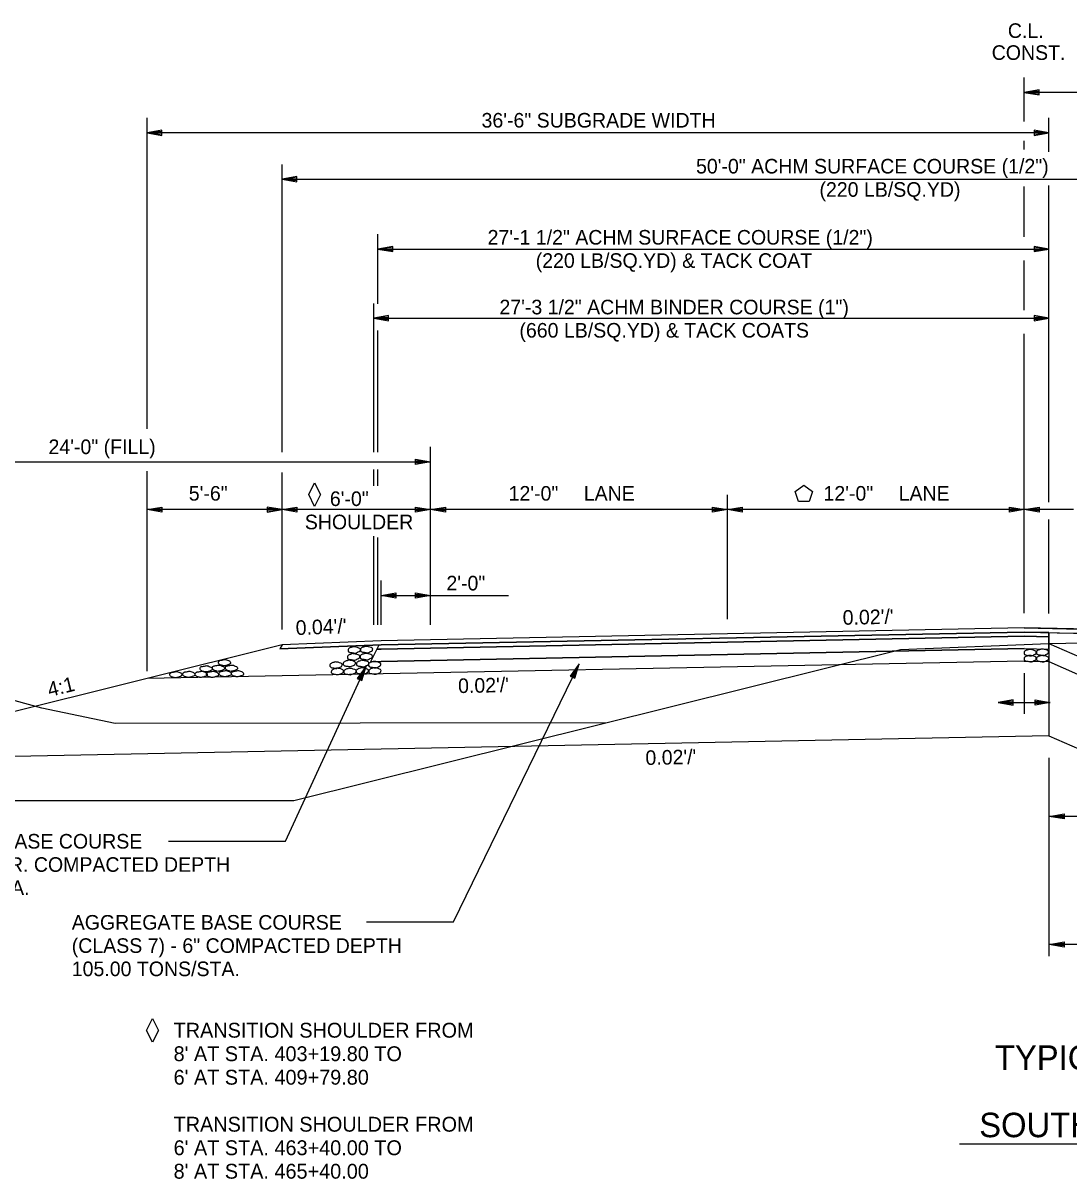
# Model space of a CAD drawing. Extents: x 1398565 to 1398920, y 1968324 to 1968581.
# Drawn here: x 1398801.5 to 1398843.78, y 1968324.35 to 1968371.07 of the extents above; entities that cross this region are included whole.
import ezdxf

# ---------------------------------------------------------------- set-up
doc = ezdxf.new("R2010")
doc.units = 0
for name, color, linetype in [('1', 7, 'Continuous'), ('10', 7, 'Continuous'), ('19', 7, 'Continuous'), ('42', 7, 'Continuous'), ('7', 7, 'Continuous'), ('Level 1', 7, 'Continuous')]:
    doc.layers.add(name, color=color, linetype=linetype)

# ---------------------------------------------------------------- blocks, each defined once
blk = doc.blocks.new('ROCKS')
at = {"layer": '1'}
blk.add_spline([(0.013, 0.06), (0.053, 0.053), (0.107, 0.033), (0.133, 0.013), (0.133, -0.007), (0.12, -0.033), (0.107, -0.04), (0.073, -0.053), (0.033, -0.067), (0.013, -0.067), (-0.02, -0.06), (-0.06, -0.053), (-0.087, -0.047), (-0.113, -0.02), (-0.113, -0.007), (-0.107, 0.02), (-0.087, 0.033), (-0.067, 0.047), (-0.033, 0.053), (-0.02, 0.06), (0.013, 0.06)], degree=3, dxfattribs=at)
blk = doc.blocks.new('4TO1 ABC')
at = {"layer": '1', "xscale": 0.1312491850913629, "yscale": 0.1312491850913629, "rotation": 180}
for p in [(0.00175, -0.00875), (-0.03325, -0.0385), (-0.016625, -0.023625), (0, -0.0385), (0.018375, -0.023625), (0.051625, -0.025375), (0.034125, -0.04025), (0.06475, -0.04025), (0.098, -0.04025), (0.133, -0.041125)]:
    blk.add_blockref('ROCKS', p, dxfattribs=at)

msp = doc.modelspace()

# ---------------------------------------------------------------- linework, layer by layer
at = {"layer": '10'}
for points in [[(1398813.286, 1968352.492), (1398813.527, 1968352.01), (1398813.286, 1968351.528), (1398813.045, 1968352.01)], [(1398832.708, 1968352.141), (1398833.058, 1968352.394), (1398833.407, 1968352.141), (1398833.274, 1968351.73), (1398832.842, 1968351.73)], [(1398806.73, 1968330.836), (1398806.971, 1968330.354), (1398806.73, 1968329.872), (1398806.489, 1968330.354)]]:
    msp.add_lwpolyline(points, close=True, dxfattribs=at)
at = {"layer": '19'}
for p, q in [((1398842.569, 1968368.374), (1398841.969, 1968368.269)), ((1398853.969, 1968368.269), (1398841.969, 1968368.269)), ((1398841.969, 1968368.269), (1398842.569, 1968368.164)), ((1398842.569, 1968368.319), (1398842.129, 1968368.284)), ((1398842.129, 1968368.254), (1398842.569, 1968368.214)), ((1398842.569, 1968368.164), (1398842.569, 1968368.374)), ((1398806.51, 1968354.67), (1398806.51, 1968367.234)), ((1398842.969, 1968365.863), (1398842.969, 1968367.234)), ((1398807.11, 1968366.739), (1398806.51, 1968366.634)), ((1398807.11, 1968366.529), (1398807.11, 1968366.739)), ((1398842.369, 1968366.739), (1398842.369, 1968366.529)), ((1398842.969, 1968366.634), (1398842.369, 1968366.739)), ((1398842.969, 1968366.634), (1398806.51, 1968366.634)), ((1398806.51, 1968366.634), (1398807.11, 1968366.529)), ((1398807.11, 1968366.684), (1398806.67, 1968366.649)), ((1398806.67, 1968366.619), (1398807.11, 1968366.579)), ((1398842.809, 1968366.649), (1398842.369, 1968366.684)), ((1398842.369, 1968366.529), (1398842.969, 1968366.634)), ((1398842.369, 1968366.579), (1398842.809, 1968366.619)), ((1398811.969, 1968353.726), (1398811.969, 1968365.359)), ((1398812.569, 1968364.864), (1398811.969, 1968364.759)), ((1398812.569, 1968364.654), (1398812.569, 1968364.864)), ((1398811.969, 1968364.759), (1398861.969, 1968364.759)), ((1398811.969, 1968364.759), (1398812.569, 1968364.654)), ((1398812.569, 1968364.809), (1398812.129, 1968364.774)), ((1398812.129, 1968364.744), (1398812.569, 1968364.704)), ((1398842.969, 1968351.707), (1398842.969, 1968364.508)), ((1398815.842, 1968359.72), (1398815.842, 1968362.537)), ((1398816.442, 1968362.042), (1398815.842, 1968361.937)), ((1398815.842, 1968361.937), (1398816.442, 1968361.832)), ((1398815.842, 1968361.937), (1398842.969, 1968361.937)), ((1398816.442, 1968361.987), (1398816.002, 1968361.952)), ((1398816.002, 1968361.922), (1398816.442, 1968361.882)), ((1398816.442, 1968361.832), (1398816.442, 1968362.042)), ((1398842.369, 1968362.042), (1398842.369, 1968361.832)), ((1398842.969, 1968361.937), (1398842.369, 1968362.042)), ((1398842.809, 1968361.952), (1398842.369, 1968361.987)), ((1398842.369, 1968361.832), (1398842.969, 1968361.937)), ((1398842.369, 1968361.882), (1398842.809, 1968361.922)), ((1398815.672, 1968353.726), (1398815.672, 1968359.739)), ((1398816.272, 1968359.244), (1398815.672, 1968359.139)), ((1398815.672, 1968359.139), (1398842.969, 1968359.139)), ((1398815.672, 1968359.139), (1398816.272, 1968359.034)), ((1398816.272, 1968359.189), (1398815.832, 1968359.154)), ((1398815.832, 1968359.124), (1398816.272, 1968359.084)), ((1398816.272, 1968359.034), (1398816.272, 1968359.244)), ((1398842.369, 1968359.244), (1398842.369, 1968359.034)), ((1398842.969, 1968359.139), (1398842.369, 1968359.244)), ((1398842.809, 1968359.154), (1398842.369, 1968359.189)), ((1398842.369, 1968359.034), (1398842.969, 1968359.139)), ((1398842.369, 1968359.084), (1398842.809, 1968359.124)), ((1398815.842, 1968353.726), (1398815.842, 1968358.646)), ((1398817.969, 1968346.74), (1398817.969, 1968353.935)), ((1398793.969, 1968353.335), (1398817.969, 1968353.335)), ((1398817.369, 1968353.23), (1398817.369, 1968353.44)), ((1398817.369, 1968353.44), (1398817.969, 1968353.335)), ((1398817.369, 1968353.385), (1398817.809, 1968353.35)), ((1398817.969, 1968353.335), (1398817.369, 1968353.23)), ((1398817.809, 1968353.32), (1398817.369, 1968353.28)), ((1398806.51, 1968344.879), (1398806.51, 1968352.964)), ((1398811.969, 1968346.559), (1398811.969, 1968352.906)), ((1398815.672, 1968352.359), (1398815.672, 1968353.023)), ((1398815.842, 1968352.359), (1398815.842, 1968353.023)), ((1398829.969, 1968346.98), (1398829.969, 1968352.003)), ((1398806.51, 1968351.403), (1398807.11, 1968351.508)), ((1398831.969, 1968351.403), (1398806.51, 1968351.403)), ((1398807.11, 1968351.298), (1398806.51, 1968351.403)), ((1398806.67, 1968351.418), (1398807.11, 1968351.453)), ((1398807.11, 1968351.348), (1398806.67, 1968351.388)), ((1398807.11, 1968351.508), (1398807.11, 1968351.298)), ((1398811.369, 1968351.508), (1398811.369, 1968351.298)), ((1398811.969, 1968351.403), (1398811.369, 1968351.508)), ((1398811.809, 1968351.418), (1398811.369, 1968351.453)), ((1398811.369, 1968351.298), (1398811.969, 1968351.403)), ((1398811.369, 1968351.348), (1398811.809, 1968351.388)), ((1398811.969, 1968351.403), (1398812.569, 1968351.508)), ((1398812.569, 1968351.298), (1398811.969, 1968351.403)), ((1398812.129, 1968351.418), (1398812.569, 1968351.453)), ((1398812.569, 1968351.348), (1398812.129, 1968351.388)), ((1398812.569, 1968351.508), (1398812.569, 1968351.298)), ((1398817.369, 1968351.298), (1398817.369, 1968351.508)), ((1398817.369, 1968351.508), (1398817.969, 1968351.403)), ((1398817.369, 1968351.453), (1398817.809, 1968351.418)), ((1398817.969, 1968351.403), (1398817.369, 1968351.298)), ((1398817.809, 1968351.388), (1398817.369, 1968351.348)), ((1398817.969, 1968351.403), (1398818.569, 1968351.508)), ((1398818.569, 1968351.298), (1398817.969, 1968351.403)), ((1398818.129, 1968351.418), (1398818.569, 1968351.453)), ((1398818.569, 1968351.348), (1398818.129, 1968351.388)), ((1398818.569, 1968351.508), (1398818.569, 1968351.298)), ((1398829.369, 1968351.298), (1398829.369, 1968351.508)), ((1398829.369, 1968351.508), (1398829.969, 1968351.403)), ((1398829.369, 1968351.453), (1398829.809, 1968351.418)), ((1398829.969, 1968351.403), (1398829.369, 1968351.298)), ((1398829.809, 1968351.388), (1398829.369, 1968351.348)), ((1398829.969, 1968351.403), (1398830.569, 1968351.508)), ((1398830.569, 1968351.298), (1398829.969, 1968351.403)), ((1398830.129, 1968351.418), (1398830.569, 1968351.453)), ((1398830.569, 1968351.348), (1398830.129, 1968351.388)), ((1398830.569, 1968351.508), (1398830.569, 1968351.298)), ((1398843.969, 1968351.403), (1398831.969, 1968351.403)), ((1398841.369, 1968351.298), (1398841.369, 1968351.508)), ((1398841.369, 1968351.508), (1398841.969, 1968351.403)), ((1398841.369, 1968351.453), (1398841.809, 1968351.418)), ((1398841.969, 1968351.403), (1398841.369, 1968351.298)), ((1398841.809, 1968351.388), (1398841.369, 1968351.348)), ((1398841.969, 1968351.403), (1398842.569, 1968351.508)), ((1398842.569, 1968351.298), (1398841.969, 1968351.403)), ((1398842.129, 1968351.418), (1398842.569, 1968351.453)), ((1398842.569, 1968351.348), (1398842.129, 1968351.388)), ((1398842.569, 1968351.508), (1398842.569, 1968351.298)), ((1398842.969, 1968347.2), (1398842.969, 1968351.004)), ((1398815.672, 1968346.74), (1398815.672, 1968350.328)), ((1398815.842, 1968346.74), (1398815.842, 1968350.27)), ((1398815.969, 1968346.74), (1398815.969, 1968348.534)), ((1398815.969, 1968347.934), (1398816.569, 1968348.039)), ((1398815.969, 1968347.934), (1398821.116, 1968347.934)), ((1398816.569, 1968347.829), (1398815.969, 1968347.934)), ((1398816.129, 1968347.949), (1398816.569, 1968347.984)), ((1398816.569, 1968347.879), (1398816.129, 1968347.919)), ((1398816.569, 1968348.039), (1398816.569, 1968347.829)), ((1398817.369, 1968347.829), (1398817.369, 1968348.039)), ((1398817.369, 1968348.039), (1398817.969, 1968347.934)), ((1398817.369, 1968347.984), (1398817.809, 1968347.949)), ((1398817.969, 1968347.934), (1398817.369, 1968347.829)), ((1398817.809, 1968347.919), (1398817.369, 1968347.879)), ((1398841.969, 1968346.62), (1398815.969, 1968346.1)), ((1398841.969, 1968346.453), (1398815.969, 1968345.933)), ((1398841.969, 1968346.287), (1398815.969, 1968345.767)), ((1398841.969, 1968346.62), (1398855.969, 1968346.34)), ((1398841.969, 1968346.453), (1398855.969, 1968346.173)), ((1398841.969, 1968346.287), (1398842.969, 1968346.267)), ((1398842.969, 1968346.267), (1398841.969, 1968346.287)), ((1398842.969, 1968346.433), (1398842.969, 1968344.975)), ((1398842.969, 1968345.767), (1398842.969, 1968346.267)), ((1398811.969, 1968345.94), (1398793.969, 1968341.44)), ((1398811.969, 1968345.94), (1398811.884, 1968345.77)), ((1398815.969, 1968345.933), (1398811.884, 1968345.77)), ((1398815.969, 1968346.1), (1398811.969, 1968345.94)), ((1398815.799, 1968345.76), (1398815.544, 1968345.25)), ((1398815.799, 1968345.76), (1398815.544, 1968345.25)), ((1398815.884, 1968345.93), (1398815.799, 1968345.76)), ((1398815.969, 1968345.767), (1398815.799, 1968345.76)), ((1398841.969, 1968345.787), (1398815.969, 1968345.267)), ((1398841.969, 1968345.787), (1398842.969, 1968345.767)), ((1398841.969, 1968345.787), (1398842.969, 1968345.767)), ((1398842.969, 1968345.993), (1398845.712, 1968344.784)), ((1398841.969, 1968345.284), (1398806.51, 1968344.575)), ((1398815.969, 1968345.267), (1398815.544, 1968345.25)), ((1398841.969, 1968345.284), (1398842.969, 1968345.264)), ((1398842.969, 1968345.264), (1398845.712, 1968344.055)), ((1398812.105, 1968338.006), (1398815.373, 1968345.072)), ((1398815.373, 1968345.072), (1398815.009, 1968344.583)), ((1398815.29, 1968344.935), (1398815.058, 1968344.562)), ((1398815.152, 1968344.513), (1398815.316, 1968344.922)), ((1398815.196, 1968344.491), (1398815.373, 1968345.072)), ((1398818.905, 1968334.747), (1398823.977, 1968345.167)), ((1398823.977, 1968345.167), (1398823.613, 1968344.678)), ((1398823.895, 1968345.03), (1398823.662, 1968344.657)), ((1398823.756, 1968344.608), (1398823.92, 1968345.017)), ((1398823.8, 1968344.586), (1398823.977, 1968345.167)), ((1398842.969, 1968344.975), (1398842.969, 1968342.264)), ((1398815.009, 1968344.583), (1398815.196, 1968344.491)), ((1398823.613, 1968344.678), (1398823.8, 1968344.586)), ((1398842.969, 1968342.264), (1398793.472, 1968341.274)), ((1398842.969, 1968342.264), (1398845.712, 1968341.055)), ((1398842.983, 1968333.357), (1398842.983, 1968341.375)), ((1398842.983, 1968339.006), (1398843.583, 1968339.111)), ((1398843.583, 1968338.901), (1398842.983, 1968339.006)), ((1398861.969, 1968339.006), (1398842.983, 1968339.006)), ((1398843.143, 1968339.021), (1398843.583, 1968339.056)), ((1398843.583, 1968338.951), (1398843.143, 1968338.991)), ((1398843.583, 1968339.111), (1398843.583, 1968338.901)), ((1398807.377, 1968338.006), (1398812.105, 1968338.006)), ((1398815.376, 1968334.747), (1398818.905, 1968334.747)), ((1398842.983, 1968333.825), (1398843.583, 1968333.93)), ((1398864.983, 1968333.825), (1398842.983, 1968333.825)), ((1398843.583, 1968333.72), (1398842.983, 1968333.825)), ((1398843.143, 1968333.84), (1398843.583, 1968333.875)), ((1398843.583, 1968333.77), (1398843.143, 1968333.81)), ((1398843.583, 1968333.93), (1398843.583, 1968333.72)), ((1398839.35, 1968325.765), (1398868.33, 1968325.765))]:
    msp.add_line(p, q, dxfattribs=at)
for points in [[(1398811.884, 1968345.77), (1398815.969, 1968345.933), (1398841.969, 1968346.453), (1398855.969, 1968346.173), (1398862.054, 1968345.93), (1398861.969, 1968346.1), (1398855.969, 1968346.34), (1398841.969, 1968346.62), (1398815.969, 1968346.1), (1398811.969, 1968345.94)], [(1398815.884, 1968345.93), (1398815.799, 1968345.76), (1398815.969, 1968345.767), (1398841.969, 1968346.287), (1398842.969, 1968346.267), (1398842.969, 1968346.433), (1398841.969, 1968346.453), (1398815.969, 1968345.933)]]:
    msp.add_lwpolyline(points, close=True, dxfattribs=at)
for points in [[(1398841.969, 1968346.287), (1398815.969, 1968345.767), (1398815.799, 1968345.76)], [(1398815.544, 1968345.25), (1398815.969, 1968345.267), (1398841.969, 1968345.787)]]:
    msp.add_lwpolyline(points, dxfattribs=at)
at = {"layer": '42'}
for p, q in [((1398841.969, 1968344.787), (1398841.969, 1968343.154)), ((1398841.522, 1968343.711), (1398840.922, 1968343.606)), ((1398840.922, 1968343.606), (1398841.522, 1968343.501)), ((1398840.922, 1968343.606), (1398843.017, 1968343.606)), ((1398841.522, 1968343.656), (1398841.082, 1968343.621)), ((1398841.082, 1968343.591), (1398841.522, 1968343.551)), ((1398841.522, 1968343.501), (1398841.522, 1968343.711)), ((1398842.417, 1968343.501), (1398842.417, 1968343.711)), ((1398842.417, 1968343.711), (1398843.017, 1968343.606)), ((1398842.417, 1968343.656), (1398842.857, 1968343.621)), ((1398843.017, 1968343.606), (1398842.417, 1968343.501)), ((1398842.857, 1968343.591), (1398842.417, 1968343.551))]:
    msp.add_line(p, q, dxfattribs=at)
for points in [[(1398825.029, 1968342.779), (1398805.225, 1968342.765), (1398802.252, 1968343.377), (1398798.325, 1968344.462), (1398790.81, 1968345.785), (1398768.049, 1968346.379)], [(1398842.969, 1968345.993), (1398853.969, 1968346.213)], [(1398765.947, 1968339.644), (1398812.443, 1968339.644), (1398836.969, 1968345.753), (1398842.969, 1968345.993)]]:
    msp.add_lwpolyline(points, dxfattribs=at)
at = {"layer": '7'}
for p, q in [((1398841.969, 1968367.09), (1398841.969, 1968368.869)), ((1398841.969, 1968365.964), (1398841.969, 1968366.309)), ((1398841.969, 1968362.425), (1398841.969, 1968364.458)), ((1398841.969, 1968359.463), (1398841.969, 1968361.471)), ((1398841.969, 1968347.22), (1398841.969, 1968358.509))]:
    msp.add_line(p, q, dxfattribs=at)

# ---------------------------------------------------------------- block references
at = {"layer": '19', "xscale": 14.999970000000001, "yscale": -14.999970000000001, "rotation": 180}
msp.add_blockref('4TO1 ABC', (1398809.65, 1968345.344), dxfattribs=at)
at = {"layer": 'Level 1', "xscale": 2.011654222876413, "yscale": 2.011654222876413, "rotation": 1.8263814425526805}
for p in [(1398814.865, 1968345.737), (1398815.363, 1968345.751), (1398842.19, 1968345.629), (1398842.688, 1968345.644), (1398814.127, 1968345.122), (1398814.67, 1968345.192), (1398814.838, 1968345.457), (1398815.203, 1968345.187), (1398815.35, 1968345.469), (1398815.694, 1968345.144), (1398842.19, 1968345.387), (1398842.694, 1968345.386), (1398814.186, 1968344.867), (1398814.691, 1968344.866), (1398815.196, 1968344.887), (1398815.7, 1968344.886)]:
    msp.add_blockref('ROCKS', p, dxfattribs=at)

# ---------------------------------------------------------------- texts
at = {"layer": '10'}
for s, height, rotation, p in [('24\'-0" (FILL)', 0.59001, 360, (1398802.527, 1968353.648)), ('5\'-6"', 0.59, 360, (1398808.199, 1968351.767)), ('12\'-0" ', 0.59, 360, (1398821.127, 1968351.767)), ('LANE', 0.59, 360, (1398824.165, 1968351.767)), ('12\'-0" ', 0.59, 360, (1398833.856, 1968351.767)), ('LANE', 0.59, 360, (1398836.894, 1968351.767)), ('6\'-0" ', 0.59, 360, (1398813.901, 1968351.549)), ('SHOULDER', 0.59, 360, (1398812.888, 1968350.609)), ('2\'-0"', 0.59, 360, (1398818.612, 1968348.138)), ('4:1', 0.59, 13.7364, (1398802.567, 1968343.83))]:
    msp.add_text(s, height=height, rotation=rotation, dxfattribs=at).set_placement(p)
at = {"layer": '19'}
msp.add_text('C.L.', height=0.59, dxfattribs=at).set_placement((1398841.309, 1968370.47))
for s, height, rotation, p in [('CONST.', 0.59, 360, (1398840.656, 1968369.582)), ("0.02'/'", 0.59, 1.1458, (1398834.637, 1968346.748)), ("0.04'/'", 0.59, 2.2906, (1398812.53, 1968346.331)), ("0.02'/'", 0.59, 1.1458, (1398819.09, 1968343.987)), ("0.02'/'", 0.59, 1.1458, (1398826.664, 1968341.08)), ('AGGREGATE BASE COURSE', 0.59001, 360, (1398795.403, 1968337.703)), ('(CLASS 7) - VAR. COMPACTED DEPTH', 0.59001, 360, (1398795.403, 1968336.763)), ('61.75 TONS/STA.', 0.59001, 360, (1398795.403, 1968335.823)), ('AGGREGATE BASE COURSE', 0.59001, 360, (1398803.467, 1968334.426)), ('(CLASS 7) - 6" COMPACTED DEPTH', 0.59001, 360, (1398803.467, 1968333.486)), ('105.00 TONS/STA.', 0.59001, 360, (1398803.467, 1968332.546)), ('TYPICAL SECTION OF IMPROVEMENT', 0.98999, 360, (1398840.787, 1968328.758)), ('SOUTHBOUND PASSING LANE (SITE 4)', 0.98999, 360, (1398840.152, 1968326.036))]:
    msp.add_text(s, height=height, rotation=rotation, dxfattribs=at).set_placement(p)
at = {"layer": '42'}
for s, p in [('36\'-6" SUBGRADE WIDTH', (1398820.033, 1968366.847)), ('50\'-0" ACHM SURFACE COURSE (1/2")', (1398828.703, 1968364.99)), ('(220 LB/SQ.YD)', (1398833.693, 1968364.049)), ('27\'-1 1/2" ACHM SURFACE COURSE (1/2")', (1398820.278, 1968362.116)), ('(220 LB/SQ.YD) & TACK COAT', (1398822.222, 1968361.176)), ('27\'-3 1/2" ACHM BINDER COURSE (1")', (1398820.756, 1968359.297)), ('(660 LB/SQ.YD) & TACK COATS', (1398821.564, 1968358.357))]:
    msp.add_text(s, height=0.59001, rotation=360, dxfattribs=at).set_placement(p)
for s, p in [('TRANSITION SHOULDER FROM', (1398807.584, 1968330.06)), ("8' AT STA. 403+19.80 TO", (1398807.584, 1968329.11)), ("6' AT STA. 409+79.80", (1398807.584, 1968328.16)), ('TRANSITION SHOULDER FROM', (1398807.584, 1968326.26)), ("6' AT STA. 463+40.00 TO", (1398807.584, 1968325.31)), ("8' AT STA. 465+40.00", (1398807.584, 1968324.36))]:
    msp.add_text(s, height=0.6, dxfattribs=at).set_placement(p)

doc.saveas('drawing.dxf')
